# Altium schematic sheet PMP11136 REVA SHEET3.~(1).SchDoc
size 431 x 279 mm; Date: Not shown in title block; ApprovedBy: Not shown in title block; CheckedBy: Not shown in title block; Author: Not shown in title block; CompanyName: Not shown in title block; Engineer: Not shown in title block; Organization: Not shown in title block; Address1: Not shown in title block; Address2: Not shown in title block; Address3: Not shown in title block; Address4: Not shown in title block; DocumentNumber: 3; Revision: Use project parameter SCH_Rev; SheetNumber: 3; SheetTotal: 3; PageSetup: Record=PageOptions¦CenterHorizontal=True¦CenterVertical=True¦PrintScale=1.00¦XCorrection=1.00¦YCorrection=1.00¦PrintKind=0¦BorderSize=5000000¦LeftOffset=0¦BottomOffset=0¦Orientation=2¦PaperLength=1000¦PaperWidth=1000¦Scale=100¦PaperSource=15¦PrintQuality=600¦MediaType=1¦DitherType=10¦PaperKind=Letter¦PrintScaleMode=1
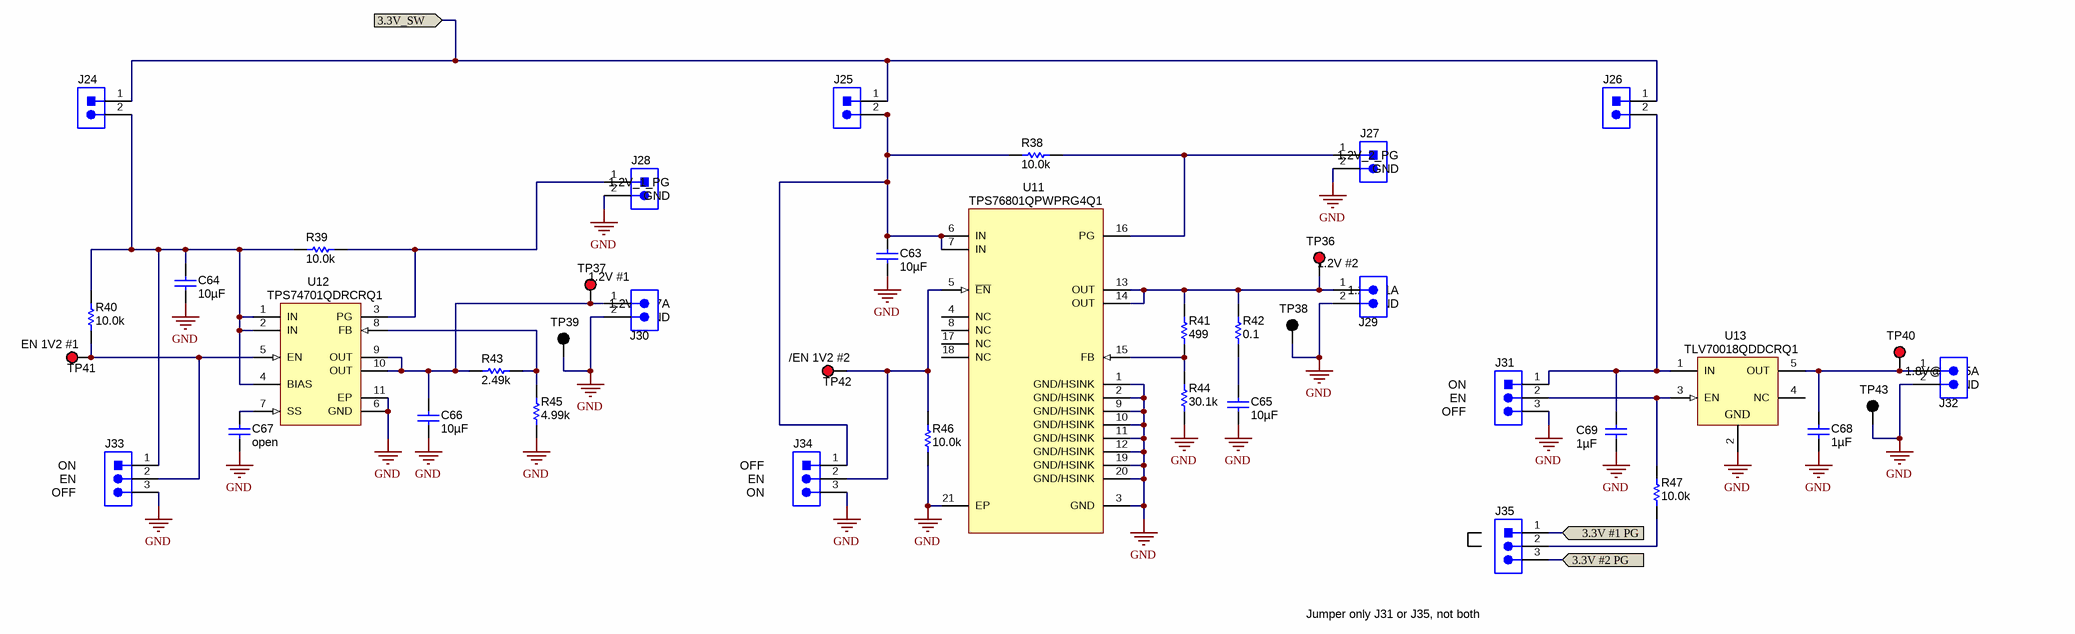
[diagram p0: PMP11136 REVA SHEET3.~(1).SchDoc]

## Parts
C63  ValueDisplayed: 10µF  [0805_HV]  (hidden comment: GRM21BR71A106KE51L)
C64  ValueDisplayed: 10µF  [0805_HV]  (hidden comment: GRM21BR71A106KE51L)
C65  ValueDisplayed: 10µF  [0805_HV]  (hidden comment: GRM21BR71A106KE51L)
C66  ValueDisplayed: 10µF  [0805_HV]  (hidden comment: GRM21BR71A106KE51L)
C67  ValueDisplayed: open  [0603]
C68  ValueDisplayed: 1µF  [0603]  (hidden comment: C1608X7R1E105K)
C69  ValueDisplayed: 1µF  [0603]  (hidden comment: C1608X7R1E105K)
J24  PEC02SAAN  [CONN_PEC02SAAN]  (value not drawn)
J25  PEC02SAAN  [CONN_PEC02SAAN]  (value not drawn)
J26  PEC02SAAN  [CONN_PEC02SAAN]  (value not drawn)
J27  PEC02SAAN  [CONN_PEC02SAAN]  (value not drawn)
J28  PEC02SAAN  [CONN_PEC02SAAN]  (value not drawn)
J29  ED555/2DS  [TERM_BLK_ED555-2DS]  (value not drawn)
J30  ED555/2DS  [TERM_BLK_ED555-2DS]  (value not drawn)
J31  PEC03SAAN  [CONN_PEC03SAAN]  (value not drawn)
J32  ED555/2DS  [TERM_BLK_ED555-2DS]  (value not drawn)
J33  PEC03SAAN  [CONN_PEC03SAAN]  (value not drawn)
J34  PEC03SAAN  [CONN_PEC03SAAN]  (value not drawn)
J35  PEC03SAAN  [CONN_PEC03SAAN]  (value not drawn)
R38  ValueDisplayed: 10.0k  [0603]  (hidden comment: CRCW060310K0FKEA)
R39  ValueDisplayed: 10.0k  [0603]  (hidden comment: CRCW060310K0FKEA)
R40  ValueDisplayed: 10.0k  [0603]  (hidden comment: CRCW060310K0FKEA)
R41  ValueDisplayed: 499  [0603]  (hidden comment: CRCW0603499RFKEA)
R42  value 0.1  [0805_HV]  (hidden comment: ERJ-6RSJR10V)
R43  ValueDisplayed: 2.49k  [0603]  (hidden comment: CRCW06032K49FKEA)
R44  ValueDisplayed: 30.1k  [0603]  (hidden comment: CRCW060330K1FKEA)
R45  ValueDisplayed: 4.99k  [0603]  (hidden comment: CRCW06034K99FKEA)
R46  ValueDisplayed: 10.0k  [0603]  (hidden comment: CRCW060310K0FKEA)
R47  ValueDisplayed: 10.0k  [0603]  (hidden comment: CRCW060310K0FKEA)
TP36  5000  [Keystone5000]  (value not drawn)
TP37  5000  [Keystone5000]  (value not drawn)
TP38  5001  [Keystone5001]  (value not drawn)
TP39  5001  [Keystone5001]  (value not drawn)
TP40  5000  [Keystone5000]  (value not drawn)
TP41  5000  [Keystone5000]  (value not drawn)
TP42  5000  [Keystone5000]  (value not drawn)
TP43  5001  [Keystone5001]  (value not drawn)
U11  TPS76801QPWPRG4Q1  [PWP0020B_N]
U12  TPS74701QDRCRQ1  [DRC0010A]
U13  TLV70018QDDCRQ1  [DDC0005A_N]

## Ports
3.3V #1 PG, 3.3V #2 PG, 3.3V_SW

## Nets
GND: C63.2 C64.2 C65.2 C66.2 C67.2 C68.2 C69.2 J27.2 J28.2 J29.2 J30.2 J31.3 J32.2 J33.3 J34.3 R44.1 R45.1 R46.1 TP38.1 TP39.1 TP43.1 U11.1(GND/HSINK) U11.2(GND/HSINK) U11.3(GND) U11.9(GND/HSINK) U11.10(GND/HSINK) U11.11(GND/HSINK) U11.12(GND/HSINK) U11.19(GND/HSINK) U11.20(GND/HSINK) U11.21(EP) U12.6(GND) U12.11(EP) U13.2(GND)
3.3V #1 PG: J35.1 ; port 3.3V #1 PG
3.3V #2 PG: J35.3 ; port 3.3V #2 PG
3.3V_SW: J24.1 J25.1 J26.1 ; port 3.3V_SW
NetC63_1: C63.1 J25.2 J34.1 R38.1 U11.6(IN) U11.7(IN)
NetC64_1: C64.1 J24.2 J33.1 R39.2 R40.2 U12.1(IN) U12.2(IN) U12.4(BIAS)
NetC65_1: C65.1 R42.1
NetC66_1: C66.1 J30.1 R43.2 TP37.1 U12.9(OUT) U12.10(OUT)
NetC67_1: C67.1 U12.7(SS)
NetC68_1: C68.1 J32.1 TP40.1 U13.5(OUT)
NetC69_1: C69.1 J26.2 J31.1 U13.1(IN)
NetJ27_1: J27.1 R38.2 U11.16(PG)
NetJ28_1: J28.1 R39.1 U12.3(PG)
NetJ29_1: J29.1 R41.1 R42.2 TP36.1 U11.13(OUT) U11.14(OUT)
NetJ31_2: J31.2 R47.2 U13.3(EN)
NetJ33_2: J33.2 R40.1 TP41.1 U12.5(EN)
NetJ34_2: J34.2 R46.2 TP42.1 U11.5(~{EN})
NetJ35_2: J35.2 R47.1
NetR41_2: R41.2 R44.2 U11.15(FB)
NetR43_1: R43.1 R45.2 U12.8(FB)

Not connected (* = marked no-connect by the designer): U11 4(NC) 8(NC) 17(NC) 18(NC); U13 4(NC)

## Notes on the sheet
- (near J28) 1.2V_1_PG
- (near J28) GND
- (near J27) 1.2V_2_PG
- (near J27) GND
- (near J30) 1.2V #1
- (near J29) 1.2V #2
- (near TP41) EN 1V2 #1
- (near J30) 1.2V@0.7A
- (near J30) GND
- (near J29) 1.2V@1A
- (near J29) GND
- (near TP42) /EN 1V2 #2
- (near J31) EN
- (near J31) ON
- (near J31) OFF
- (near J32) 1.8V@0.155A
- (near J32) GND
- (near J33) EN
- (near J33) ON
- (near J34) EN
- (near J34) OFF
- (near J33) OFF
- (near J34) ON
- (near J35) Jumper only J31 or J35, not both

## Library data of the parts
C63-C66 = GRM21BR71A106KE51L: CAP, CERM, 10 µF, 10 V, +/- 10%, X7R, 0805; Manufacturer: MuRata; Polarized: N; CompType: Capacitor; Value: 10uF; U/M: EA; Cap_F: 0.00001; Tolerance_%: 10; ESR_ohm: 0.003; Value1: 0.003 ohm; Value2: 10V; TaMin_C: -55; TaMax_C: 125; Cap_Case: 0805
C67 = C1608C0G1H102J: CAP, CERM, open, 0603; Polarized: N; CompType: Capacitor; U/M: EA; Cap_F: 0.000000001; Tolerance_%: 5; ESR_ohm: 0.0563; TempCo: C0G/NP0; TaMin_C: -55; TaMax_C: 125
C68 C69 = C1608X7R1C105K: CAP, CERM, 1uF, 25V, +/-10%, X7R, 0603; Manufacturer: TDK; Polarized: N; CompType: Capacitor; U/M: EA; Cap_F: 0.000001; Tolerance_%: 10; ESR_Ohm: 0.0057; Value1: 0.0057 ohm; VDC_V: 25; TaMin_C: -55; TaMax_C: 125
J24-J28 = PEC02SAAN: Header, 100mil, 2x1, Tin, TH; Manufacturer: Sullins Connector Solutions; SymbolCreator: a0412235; U/M: EA
J29 J30 J32 = ED555/2DS: Terminal Block, 6A, 3.5mm Pitch, 2-Pos, TH; Manufacturer: On-Shore Technology, Inc.; SymbolCreator: a0412235; CompType: Connector; U/M: EA
J31 J33-J35 = PEC03SAAN: Header, 100mil, 3x1, Tin, TH; Manufacturer: Sullins Connector Solutions; SymbolCreator: a0799628; U/M: EA
R38-R40 R46 R47 = CRCW060310K0FKEA: RES, 10.0 k, 1%, 0.1 W, 0603; Manufacturer: Vishay-Dale; CompType: Resistor; Value: 10.0k; Res_ohm: 10000; Value_Code: 10k0; Tolerance_%: 1; Power_W: 0.1; Value2: 0.1W; VDC_V: 75; TempCo: 100 ppm/C; EIA_Code: E96; U/M: EA
R41 = CRCW0603499RFKEA: RES, 499, 1%, 0.1 W, 0603; Manufacturer: Vishay-Dale; CompType: Resistor; Value: 499; Value_Code: 499R; Tolerance_%: 1; Power_W: 0.1; Value2: 0.1W; VDC_V: 75; TempCo: 100 ppm/C; EIA_Code: E96; U/M: EA
R42 = ERJ-6RSJR10V: RES, 0.1 ohm, 5%, 0.125W, 0805; Manufacturer: Panasonic; CompType: Resistor; Value_Code: R100; Tolerance_%: 5; Power_W: 0.125; TempCo: 250 ppm/C; EIA_Code: E24; U/M: EA
R43 = CRCW06032K49FKEA: RES, 2.49 k, 1%, 0.1 W, 0603; Manufacturer: Vishay-Dale; CompType: Resistor; Value: 2.49k; Res_ohm: 2490; Value_Code: 2k49; Tolerance_%: 1; Power_W: 0.1; Value2: 0.1W; VDC_V: 75; TempCo: 100 ppm/C; EIA_Code: E96; U/M: EA
R44 = CRCW060330K1FKEA: RES, 30.1 k, 1%, 0.1 W, 0603; Manufacturer: Vishay-Dale; CompType: Resistor; Value: 30.1k; Res_ohm: 30100; Value_Code: 30k1; Tolerance_%: 1; Power_W: 0.1; Value2: 0.1W; VDC_V: 75; TempCo: 100 ppm/C; EIA_Code: E96; U/M: EA
R45 = CRCW06034K99FKEA: RES, 4.99 k, 1%, 0.1 W, 0603; Manufacturer: Vishay-Dale; CompType: Resistor; Value: 4.99k; Res_ohm: 4990; Value_Code: 4k99; Tolerance_%: 1; Power_W: 0.1; Value2: 0.1W; VDC_V: 75; TempCo: 100 ppm/C; EIA_Code: E96; U/M: EA
TP36 TP37 TP40-TP42 = 5000: Test Point, TH, Miniature, Red; Manufacturer: Keystone; CompType: Test Point Loop; U/M: EA
TP38 TP39 TP43 = 5001: Test Point, TH, Miniature, Black; Manufacturer: Keystone; CompType: Test Point Loop; U/M: EA
U11 = TPS76801QPWPRG4Q1: Single Output Automotive LDO, 1 A, Adjustable 1.2 to 5.5 V Output, 2.7 to 10 V Input, 20-pin HTSSOP (PWP), -40 to 125 degC, Green (RoHS & no Sb/Br); Manufacturer: Texas Instruments; Alternate Manufacturer: None; Alternate PartNumber: Equivalent; Accuracy(%): 2; Iout(Max)(A): 1; Iq(Typ)(mA): 0.08; Power Good: TRUE; SubFamily: Single Channel LDO; Vdo(Typ)(mV): 230; Vin(Max)(V): 10; Vin(Min)(V): 2.7; Vout Adj(Max)(V): 5.5; Vout Adj(Min)(V): 1.2
U12 = TPS74701QDRCRQ1: Single Output Automotive LDO, 500 mA, Adjustable 0.8 to 3.6 V Output, 0.8 to 5.5 V Input, with Programmable Soft Start, 10-pin SON (DRC), -40 to 125 degC, Green (RoHS & no Sb/Br); Manufacturer: Texas Instruments; Alternate Manufacturer: None; Alternate PartNumber: Equivalent; Accuracy(%): 2; Iout(Max)(A): 0.5; Iq(Typ)(mA): 1; SubFamily: Single Channel LDO; Vdo(Typ)(mV): 50; Vin(Max)(V): 5.5; Vin(Min)(V): 0.8; Vout Adj(Max)(V): 3.6
U13 = TLV70018QDDCRQ1: Single Output Automotive LDO, 300 mA, Fixed 1.8 V Output, 2 to 5.5 V Input, with Low IQ, 5-pin SOT (DDC), -40 to 125 degC, Green (RoHS & no Sb/Br); Manufacturer: Texas Instruments; Alternate Manufacturer: None; Alternate PartNumber: Equivalent; Accuracy(%): 2; Fixed Output Options(V): 1.8; Iout(Max)(A): 0.2; Iq(Typ)(mA): 0.03; SubFamily: Single Channel LDO; Vdo(Typ)(mV): 175; Vin(Max)(V): 5.5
